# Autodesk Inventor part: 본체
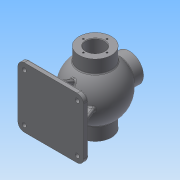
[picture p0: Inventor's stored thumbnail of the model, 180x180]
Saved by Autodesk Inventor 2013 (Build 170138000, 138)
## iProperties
Created: 2018-06
Part Number: 본체
Material: 일반
Document SubType Name: Modeling
Designer: Administrator
Density: 1 g/cm^3
Author: Administrator
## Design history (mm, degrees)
sketch "스케치1"
  geometry: L1 (0, 68)-(0, -68); L2 (0, 68)-(31, 68); L3 (31, -68)-(0, -68); L4 (31, 68)-(31, 42.988); L5 (31, -42.988)-(31, -68); L6 (17.5, 68)-(17.5, 39.278); L7 (17.5, -39.278)-(17.5, -68); A1 r 53 centre (0, 0) between (31, -42.988) and (31, 42.988); A2 r 43 centre (0, 0) between (17.5, -39.278) and (17.5, 39.278); 2 further points
  constraints: 14 end point, 4 point on circle, 2 centre point, 2 coincident, 2 point on line, 1 concentric, 1 midpoint, 1 vertical alignment
  dimensions: "d0" = 136 distance of L1.start L1.end; "d1" = 106 diameter of A1; "d2" = 86 diameter of A2; "d3" = 62 diameter of L4 L1; "d4" = 62 diameter of L5 L1; "d5" = 136 distance between parallel lines of L3 L2; "d6" = 35 diameter of L6 L1; "d7" = 35 diameter of L7 L1
revolve "회전1" sketch "스케치1" stored, may be unused: angle "d8" = 90 deg
node "작업 평면1"
sketch "스케치2"
  geometry: L1 (-62.5, -57.5)-(62.5, -57.5); L2 (62.5, -57.5)-(62.5, 57.5); L3 (62.5, 57.5)-(-62.5, 57.5); L4 (-62.5, 57.5)-(-62.5, -57.5); L5 (-62.5, -57.5)-(62.5, 57.5); L6 (62.5, -57.5)-(-62.5, 57.5); 3 further points
  constraints: 12 end point, 3 midpoint, 2 parallel, 1 coincident, 1 horizontal, 1 perpendicular
  dimensions: "d10" = 125 distance of L3.end L2.end; "d11" = 115 distance of L2.end L1.end
extrude "돌출1" join sketch "스케치2" distance "d12" = 10; taper "d13" = 0 deg
fillet "모깎기1" dims "d14" = 12
node "작업 평면2"
sketch "스케치3"
  geometry: C1 r 27 at (0, 0); 1 further point
  constraints: 1 centre point, 1 coincident
  dimensions: "d16" = 54 diameter of C1
extrude "돌출2" join sketch "스케치3" stored distance "d17" = 10; taper "d18" = 0 deg
hole "구멍1" diameter "d21" = 26; stored, may be unused: countersink angle "d25" = 90 deg, drill point angle "d27" = 0 deg; dims "d19" = 10, "d20" = 10, "d22" = 6, "d23" = 4, "d24" = 2, "d26" = 45
sketch "스케치5"
  geometry: C1 r 31 at (0, 0) reference; 1 further point
  constraints: 1 vertical alignment
  dimensions: "d32" = 22.5 distance of C1.centre point (0, 22.5)
hole "구멍2" sketch "스케치5" at (0, 22.5) diameter "d33" = 3.242; stored, may be unused: countersink angle "d37" = 90 deg, drill point angle "d39" = 118 deg; dims "d34" = 12, "d35" = 4, "d36" = 2, "d38" = 15
sketch "스케치6"
  geometry: L1 (-52.5, -4)-(52.5, -4); L2 (52.5, -4)-(52.5, 4); L3 (52.5, 4)-(-52.5, 4); L4 (-52.5, 4)-(-52.5, -4); L5 (-52.5, -4)-(52.5, 4); L6 (52.5, -4)-(-52.5, 4); 3 further points
  constraints: 12 end point, 3 midpoint, 2 parallel, 1 coincident, 1 horizontal, 1 perpendicular
  dimensions: "d43" = 105 distance of L3.end L2.end; "d44" = 8 distance of L2.end L1.end
extrude "돌출3" join sketch "스케치6" stored distance "d45" = 10; taper "d46" = 0 deg
feature "면 기울기1" dims angle "d47" = 22 deg
sketch "스케치7"
  geometry: L1 (-48.75, 36.894)-(-75, 47.5); L2 (-75, -45.5)-(-75, 45.5) reference; L3 (-85, 57.5)-(-75, 57.5) reference; 1 further point
  constraints: 2 end point, 1 point on line
  dimensions: "d48" = 22 deg angle of L3 L1; "d49" = 10 distance from line of L3 L1.end
feature "리브1" sketch "스케치7" dims "d50" = 1, "d51" = 8, "d52" = 0, "d53" = 0, "d54" = 1, "d55" = 1
sketch "스케치8"
  geometry: C1 r 17.5 at (0, 0) reference; 1 further point
  constraints: 1 vertical alignment
  dimensions: "d56" = 24 distance of C1.centre point (0, 24)
hole "구멍3" sketch "스케치8" at (0, 24) diameter "d57" = 3.242; stored, may be unused: countersink angle "d61" = 90 deg, drill point angle "d63" = 118 deg; dims "d58" = 16, "d59" = 4, "d60" = 2, "d62" = 19
sketch "스케치9"
  geometry: C1 r 13 at (0, 0) reference; 1 further point
  constraints: 1 vertical alignment
  dimensions: "d67" = 20 distance of C1.centre point (0, 20)
hole "구멍4" sketch "스케치9" at (0, 20) diameter "d68" = 3.242; stored, may be unused: countersink angle "d72" = 90 deg, drill point angle "d74" = 118 deg; dims "d69" = 9, "d70" = 4, "d71" = 2, "d73" = 11
node "작업 평면4"
sketch "스케치10"
  geometry: L1 (-65, -27)-(-65, 27) reference; 3 further points
  constraints: 1 horizontal alignment, 1 midpoint, 1 other
  dimensions: "d80" = 10 distance from line of point (-55, 0) L1
feature "엠보싱1" sketch "스케치10" dims "d0" = 136, "d12" = 10, "d81" = 0.5, "d82" = 0
node "작업 평면5"
sketch "스케치11"
  geometry: C1 r 18.5 at (0, 0); 1 further point
  constraints: 1 centre point, 1 coincident
  dimensions: "d84" = 37 diameter of C1
extrude "돌출4" cut sketch "스케치11" distance "d85" = 1.75; taper "d86" = 0 deg
fillet "모깎기2" dims "d87" = 3
fillet "모깎기3" dims "d88" = 3
fillet "모깎기4" dims "d89" = 3
fillet "모깎기5" dims "d90" = 3
chamfer "모따기1" distance "d91" = 1; stored, may be unused: second distance "d92" = 2, angle "d93" = 45 deg
chamfer "모따기2" distance "d94" = 1; stored, may be unused: second distance "d95" = 2, angle "d96" = 45 deg
hole "구멍5" diameter "d99" = 8; stored, may be unused: countersink angle "d103" = 90 deg, drill point angle "d105" = 0 deg; dims "d97" = 10, "d98" = 10, "d100" = 9, "d101" = 12, "d102" = 3, "d104" = 10
fillet "모깎기6" dims "d106" = 3
fillet "모깎기7" dims "d107" = 3
node "솔리드1"
pattern_circular "원형 패턴1" dims angle "d41" = 360 deg
mirror "대칭1"
pattern_circular "원형 패턴2" dims angle "d65" = 360 deg
pattern_circular "원형 패턴3" dims angle "d76" = 360 deg
mirror "대칭2"
mirror "대칭3"
other parameters: "d9" = -85, "d79" = -27, "d83" = -16
